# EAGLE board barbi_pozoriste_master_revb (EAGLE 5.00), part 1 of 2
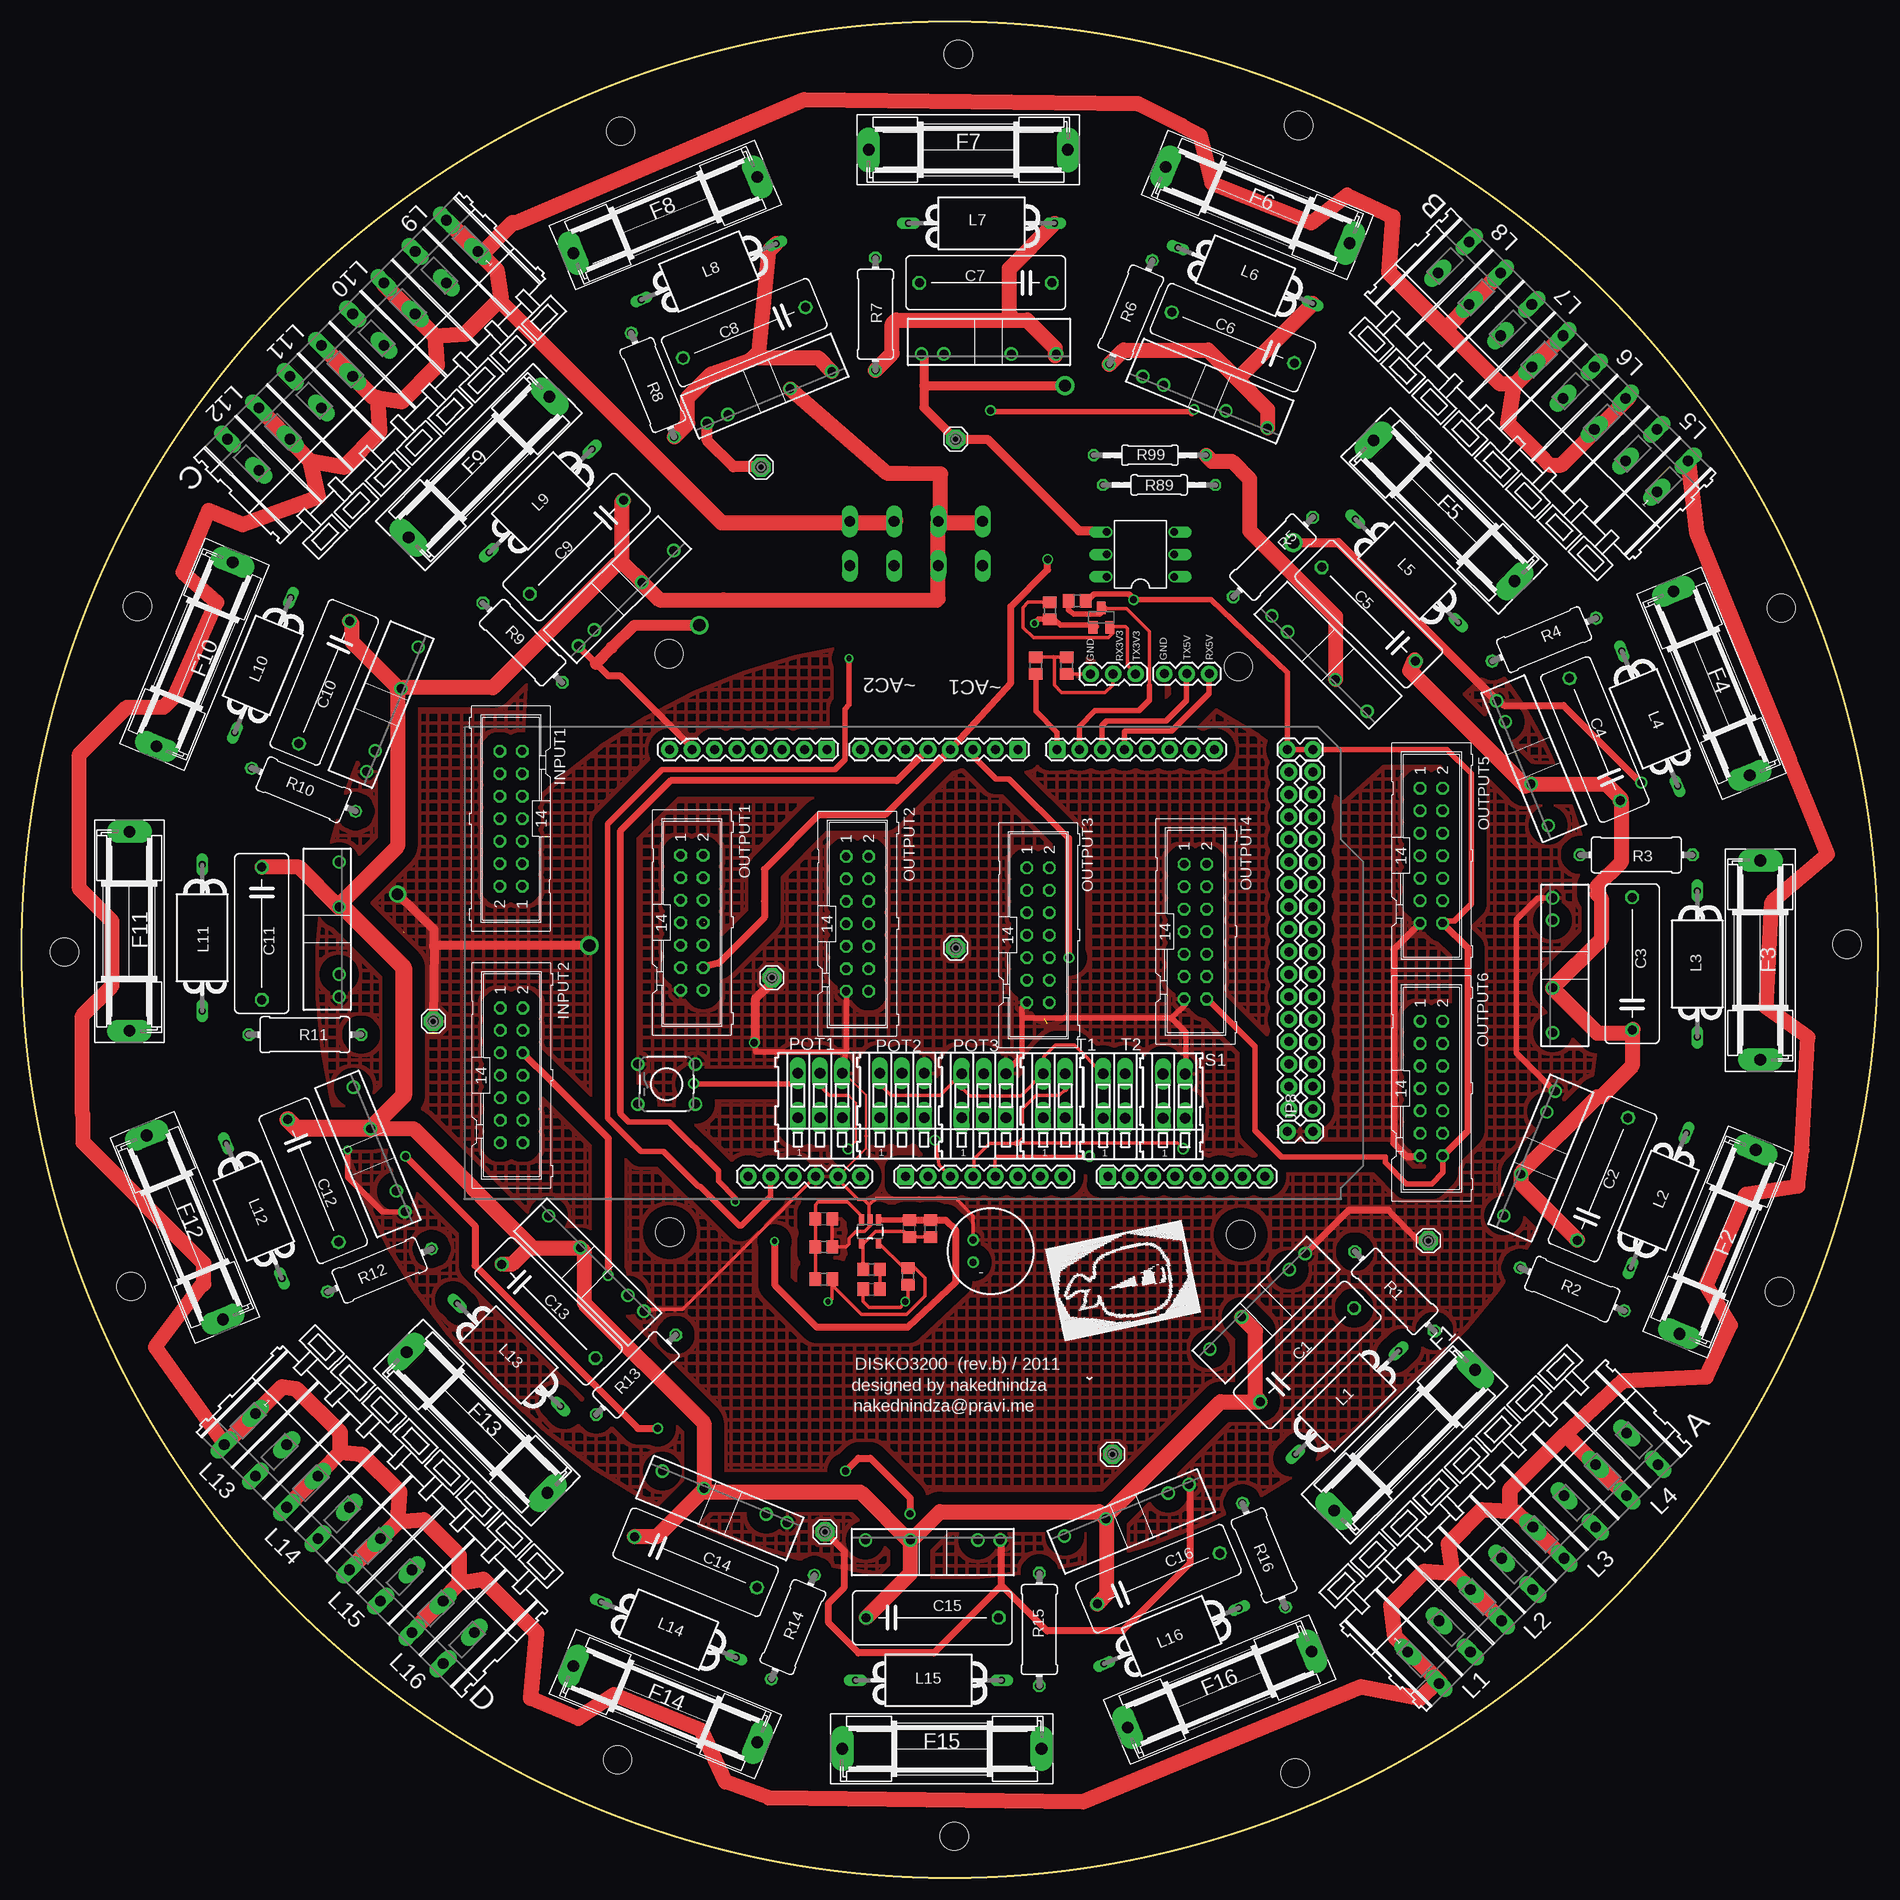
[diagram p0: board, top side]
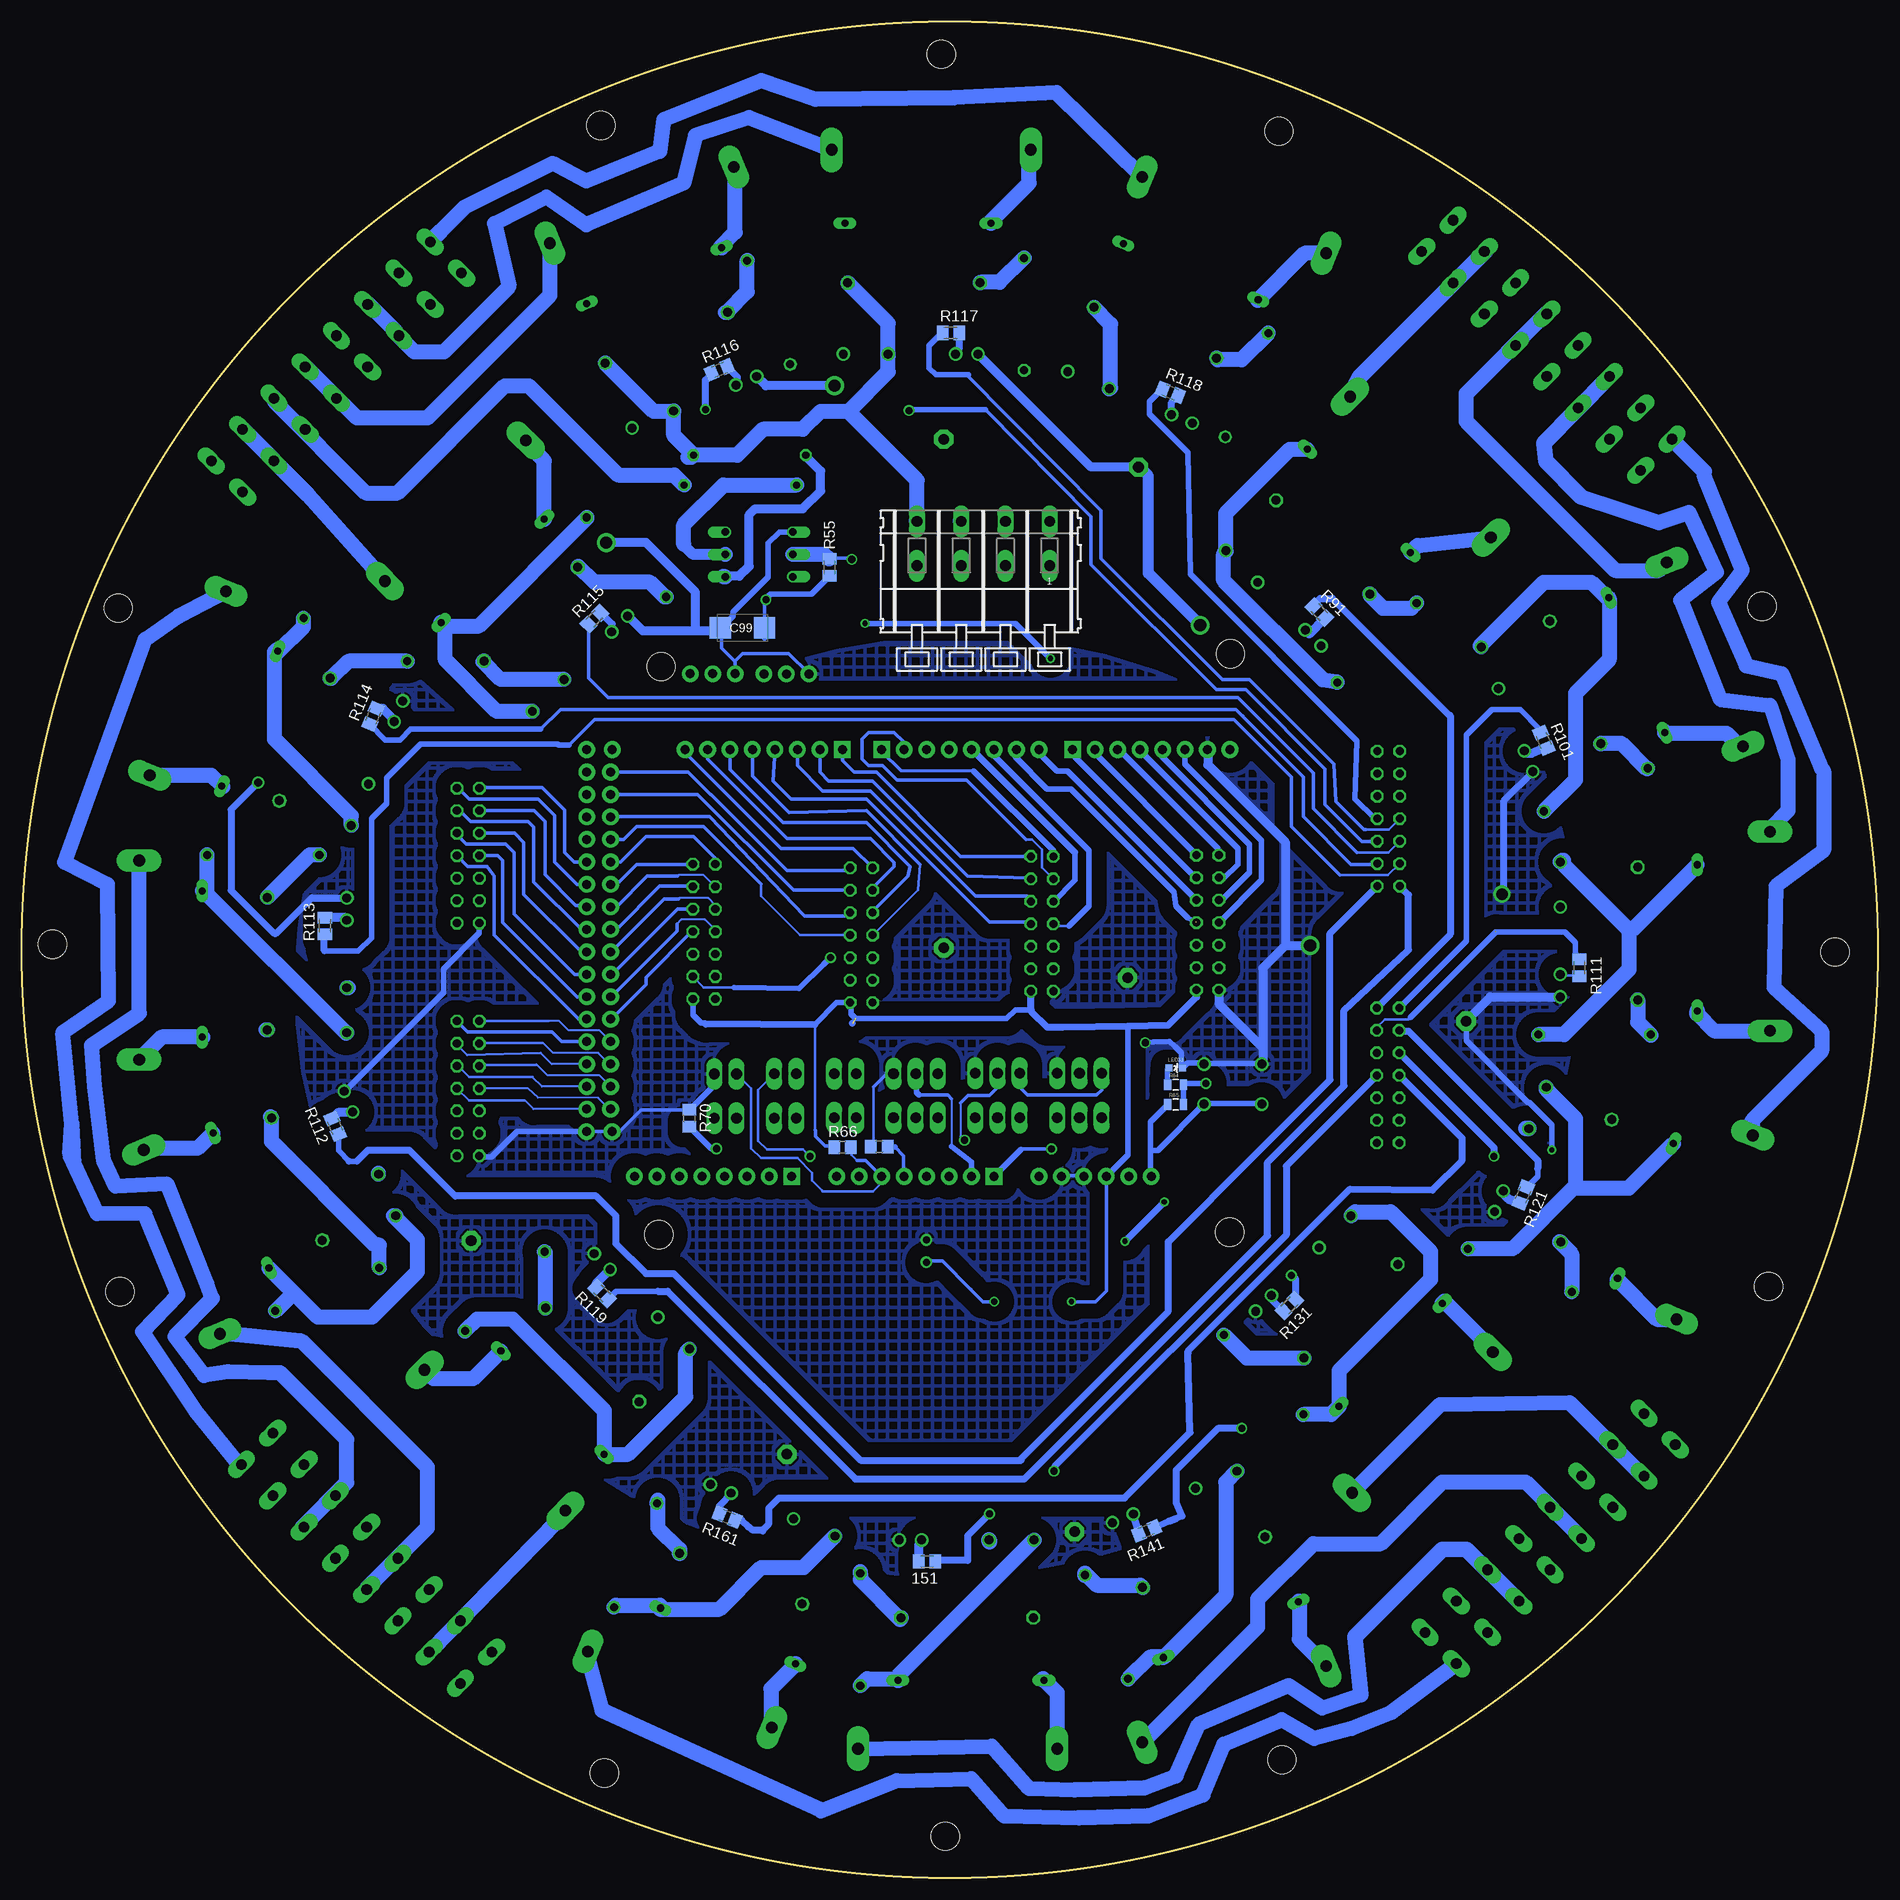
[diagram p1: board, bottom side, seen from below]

No outline drawn. Coordinates in mm, seen from the top.
Copper layers (1*16): Top 0.035mm / dielectric 1.5mm / Bottom 0.035mm
Design rules "default": minimum track width 10mil, minimum drill 24mil, track to track 8mil, track to pad 8mil, pad to pad 8mil, via to via 8mil, smd to smd 8mil, copper to edge 40mil, drill to drill 8mil, minimum pad ring 10mil, minimum via ring 8mil, stop-mask expansion 4mil, vias tented up to drill 0mil, thermal gap 10mil
Holes 3.2 mm at -32.4,33.23 32.21,-32.42 -32.33,-32.15 31.94,31.79 -37.88,92.31 38.37,-93.28 -93.23,-38.28 -38.24,-91.8 38.76,92.95 93.31,38.39 -92.5,38.6 93.12,-38.88 0.27,101 -100.74,-0.47 -0.17,-100.44 100.73,0.41
Milling: area -105.5,-105.1 to 104.2,104.6

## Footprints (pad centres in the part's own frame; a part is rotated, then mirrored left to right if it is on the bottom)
M0805 = smd 1.3 x 1.6: 1 -0.95,0; 2 0.95,0
C150-064X183 = drill 1.016 octagon: 1 -7.493,0; 2 7.493,0
C0805 = smd 1.3 x 1.5: 1 -0.95,0; 2 0.95,0
SMC_C = smd 2.4 x 2.4: + -2.5,0; - 2.5,0
SH22,5 = drill 1.321 pad 2.54 long: 1 -11.252,0; 2 11.252,0
1X03 = drill 1.016 pad 1.88 round: 1 0,0; 2 2.54,0; 3 5.08,0
1X08 = drill 1.016 pad 1.88 square: 1 0,0 | drill 1.016 pad 1.88 round: 2 2.54,0; 3 5.08,0; 4 7.62,0; 5 10.16,0; 6 12.7,0; 7 15.24,0; 8 17.78,0
1X16 = drill 1.016 pad 1.88 round: 1 0,0; 2 2.54,0; 3 5.08,0; 4 7.62,0; 5 10.16,0; 6 12.7,0; 7 15.24,0; 8 17.78,0; 9 20.32,0; 10 22.86,0; 11 25.4,0; 12 27.94,0; 13 30.48,0; 14 33.02,0; 15 35.56,0; 16 38.1,0
1X06 = drill 1.016 pad 1.88 round: 1 0,0; 2 2.54,0; 3 5.08,0; 4 7.62,0; 5 10.16,0; 6 12.7,0
1X02_LOCK = drill 1.016 pad 1.88 round: 1 -0.178,0; 2 2.718,0
S102S01 = drill 1 round: 1 -7.62,0; 2 -2.54,0; 3 5.08,0; 4 7.62,0
ZD6-2W5 = drill 0.8 long: 1 -8.255,0; 2 8.255,0
LED-0603 = smd 0.8 x 0.8: A 0,-0.75; C 0,0.75
MCS08 = drill 1.194 pad 2.159 octagon: MP 0,0
DIL06 = drill 0.813 offset: 1 -2.54,-3.81; 2 0,-3.81; 3 2.54,-3.81; 4 2.54,3.81; 5 0,3.81; 6 -2.54,3.81
SOT23 = smd 1 x 1.4: 1 -0.95,-1.1; 2 0.95,-1.1; 3 0,1.1
0411/12 = drill 0.914 octagon: 1 -6.35,0; 2 6.35,0
R0805 = smd 1.3 x 1.5: 1 -0.95,0; 2 0.95,0
0805 = smd 0.8 x 1.2: 1 -0.9,0; 2 0.9,0
0207/12 = drill 0.813 octagon: 1 -6.35,0; 2 6.35,0
TACTILE-PTH = drill 1.016 round: 1 -3.251,2.261; 2 3.251,2.261; 3 -3.251,-2.261; 4 3.251,-2.261
ML14 = drill 0.914 octagon: 1 -7.62,-1.27; 2 -7.62,1.27; 3 -5.08,-1.27; 4 -5.08,1.27; 5 -2.54,-1.27; 6 -2.54,1.27; 7 0,-1.27; 8 0,1.27; 9 2.54,-1.27; 10 2.54,1.27; 11 5.08,-1.27; 12 5.08,1.27; 13 7.62,-1.27; 14 7.62,1.27
MIC-9.7MM = drill 0.8 round: 1 -2,1.27; 2 -2,-1.27
SOT23-5 = smd 0.55 x 1.2: 1 -0.95,-1.3; 2 0,-1.3; 3 0.95,-1.3; 4 0.95,1.3; 5 -0.95,1.3
255-404-5 = drill 1.2 long: A1 -7.5,0; A2 -2.5,0; A3 2.5,0; A4 7.5,0; B1 -7.5,-5; B2 -2.5,-5; B3 2.5,-5; B4 7.5,-5
255-408-5 = drill 1.2 long: A1 -17.5,0; A2 -12.5,0; A3 -7.5,0; A4 -2.5,0; A5 2.5,0; A6 7.5,0; A7 12.5,0; A8 17.5,0; B1 -17.5,-5; B2 -12.5,-5; B3 -7.5,-5; B4 -2.5,-5; B5 2.5,-5; B6 7.5,-5; B7 12.5,-5; B8 17.5,-5
233-103 = drill 1.2 long: A1 -2.5,2.5; A2 0,2.5; A3 2.5,2.5; B1 -2.5,-2.5; B2 0,-2.5; B3 2.5,-2.5
233-102 = drill 1.2 long: A1 -1.25,2.5; A2 1.25,2.5; B1 -1.25,-2.5; B2 1.25,-2.5

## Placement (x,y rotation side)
151  330R  [M0805]  1.88,-69.37 180 bottom
C1  68nF  [C150-064X183]  39.73,-46.02 45 top
C2  68nF  [C150-064X183]  73.11,-26.14 67.5 top
C3  68nF  [C150-064X183]  76.46,-1.79 90 top
C4  68nF  [C150-064X183]  72.24,23.54 112.5 top
C5  68nF  [C150-064X183]  46.68,37.73 135 top
C6  68nF  [C150-064X183]  31.33,68.96 157.5 top
C7  68nF  [C150-064X183]  3.38,75.17 180 top
C8  68nF  [C150-064X183]  -23.91,69.53 202.5 top
C9  68nF  [C150-064X183]  -42.85,45.3 225 top
C10  68nF  [C150-064X183]  -71.38,30 247.5 top
C11  68nF  [C150-064X183]  -78.45,1.61 270 top
C12  68nF  [C150-064X183]  -72.62,-26.34 292.5 top
C13  68nF  [C150-064X183]  -46.03,-41.08 315 top
C14  68nF  [C150-064X183]  -29.4,-69.45 337.5 top
C15  68nF  [C150-064X183]  -2.64,-75.73 0 top
C16  68nF  [C150-064X183]  22.92,-71.3 22.5 top
C17  4.7uF  [C0805]  -9.52,-38.58 0 top
C18  12pF  [C0805]  -5.24,-31.75 90 top
C19  1uF  [C0805]  -14.92,-30.64 180 top
C99  47uF  [SMC_C]  22.74,36.17 180 bottom
F1  3A  [SH22,5]  50.73,-55.68 225 top
F2  3A  [SH22,5]  86.12,-33.24 247.5 top
F3  3A  [SH22,5]  90.94,-1.38 90 top
F4  3A  [SH22,5]  85.45,29.88 112.5 top
F5  3A  [SH22,5]  55.21,49.4 315 top
F6  3A  [SH22,5]  34.11,83.96 337.5 top
F7  3A  [SH22,5]  1.42,90.2 0 top
F8  3A  [SH22,5]  -32.84,82.81 22.5 top
F9  3A  [SH22,5]  -53.89,54.33 45 top
F10  3A  [SH22,5]  -86.03,33.17 67.5 top
F11  3A  [SH22,5]  -93.42,1.87 90 top
F12  3A  [SH22,5]  -87.15,-31.6 112.5 top
F13  3A  [SH22,5]  -54.11,-53.65 315 top
F14  3A  [SH22,5]  -32.83,-85.5 337.5 top
F15  3A  [SH22,5]  -1.57,-90.53 0 top
F16  3A  [SH22,5]  29.84,-83.84 22.5 top
JP1  [1X03]  23.57,30.97 0 top
JP2  [1X03]  15.24,30.96 0 top
JP3  [1X08]  -14.57,22.41 180 top
JP4  [1X08]  7.02,22.41 180 top
JP5  [1X08]  11.46,22.41 0 top
JP6  [1X08]  17.18,-25.85 0 top
JP7  [1X08]  -5.68,-25.85 0 top
JP8  M16PTH  [1X16]  40.36,-18.23 90 top
JP9  M16PTH  [1X16]  37.66,-18.23 90 top
JP10  [1X06]  -23.46,-25.85 0 top
JP11  [1X02_LOCK]  37.67,-20.77 0 top
JP12  [1X02_LOCK]  37.65,22.41 0 top
K1  S202S01  [S102S01]  34.12,-39.96 45 top
K2  S202S01  [S102S01]  64.87,-23.25 67.5 top
K3  S202S01  [S102S01]  67.48,-1.98 90 top
K4  S202S01  [S102S01]  64.06,20.87 112.5 top
K5  S202S01  [S102S01]  41.12,32.11 135 top
K6  S202S01  [S102S01]  28.19,61.66 157.5 top
K7  S202S01  [S102S01]  3.74,67.11 180 top
K8  S202S01  [S102S01]  -21.06,62.22 202.5 top
K9  S202S01  [S102S01]  -37.27,39.52 225 top
K10  S202S01  [S102S01]  -63.68,26.96 247.5 top
K11  S202S01  [S102S01]  -69.69,2.08 270 top
K12  S202S01  [S102S01]  -65.18,-22.79 292.5 top
K13  S202S01  [S102S01]  -40.64,-35.69 315 top
K14  S202S01  [S102S01]  -26.12,-62.07 337.5 top
K15  S202S01  [S102S01]  -2.58,-66.94 0 top
K16  S202S01  [S102S01]  19.33,-63.58 22.5 top
L1  300uH  [ZD6-2W5]  44.22,-51.41 45 top
L2  300uH  [ZD6-2W5]  79.44,-28.56 67.5 top
L3  300uH  [ZD6-2W5]  83.81,-1.83 270 top
L4  300uH  [ZD6-2W5]  78.45,25.89 292.5 top
L5  300uH  [ZD6-2W5]  50.99,42.6 135 top
L6  300uH  [ZD6-2W5]  32.73,75.97 157.5 top
L7  300uH  [ZD6-2W5]  2.91,81.89 180 top
L8  300uH  [ZD6-2W5]  -27.92,76.44 202.5 top
L9  300uH  [ZD6-2W5]  -46.93,50.52 225 top
L10  300uH  [ZD6-2W5]  -78.33,31.94 247.5 top
L11  300uH  [ZD6-2W5]  -85.17,1.12 270 top
L12  300uH  [ZD6-2W5]  -79.33,-29.75 292.5 top
L13  300uH  [ZD6-2W5]  -50.52,-46.02 135 top
L14  300uH  [ZD6-2W5]  -32.45,-77.07 157.5 top
L15  300uH  [ZD6-2W5]  -3.07,-82.8 180 top
L16  300uH  [ZD6-2W5]  24.39,-77.79 202.5 top
LED33  Red  [LED-0603]  -26.21,-13.58 270 bottom
LSP1  MCS08  [MCS08]  -20.79,-3.38 315 top
LSP2  MCS08  [MCS08]  -14.8,-66 315 top
LSP3  MCS08  [MCS08]  53.43,-33.11 315 top
LSP4  MCS08  [MCS08]  0,-0.01 315 top
LSP5  MCS08  [MCS08]  -0.01,57.48 315 top
LSP6  MCS08  [MCS08]  -22.01,54.33 315 top
LSP7  MCS08  [MCS08]  -59.05,-8.3 315 top
LSP8  MCS08  [MCS08]  17.73,-57.25 315 top
OK1  H11A1M  [DIL06]  20.87,44.47 90 top
Q1  BSS123  [SOT23]  16.45,37.34 0 top
R1  120R 2W  [0411/12]  49.61,-38.84 135 top
R2  120R 2W  [0411/12]  69.68,-38.6 337.5 top
R3  120R 2W  [0411/12]  76.92,10.5 0 top
R4  120R 2W  [0411/12]  66.5,34.84 22.5 top
R5  120R 2W  [0411/12]  35.86,44.16 45 top
R6  120R 2W  [0411/12]  19.79,71.82 247.5 top
R7  120R 2W  [0411/12]  -9.08,71.62 270 top
R8  120R 2W  [0411/12]  -34.25,63.61 292.5 top
R9  120R 2W  [0411/12]  -48.96,34.49 135 top
R10  120R 2W  [0411/12]  -73.71,17.86 337.5 top
R11  120R 2W  [0411/12]  -73.57,-9.82 0 top
R12  120R 2W  [0411/12]  -65.13,-36.46 22.5 top
R13  120R 2W  [0411/12]  -36.15,-48.27 225 top
R14  120R 2W  [0411/12]  -18.41,-76.78 247.5 top
R15  120R 2W  [0411/12]  9.44,-77.06 270 top
R16  120R 2W  [0411/12]  34.84,-68.66 292.5 top
R17  2k2  [R0805]  -5.4,-37.15 90 top
R18  10k  [R0805]  9.05,31.91 90 top
R19  10k  [R0805]  12.54,31.91 270 top
R20  10k  [R0805]  -9.53,-36.35 0 top
R21  10k  [R0805]  -14.92,-37.46 0 top
R22  10k  [R0805]  -14.92,-33.81 180 top
R23  1M  [R0805]  -2.86,-31.75 270 top
R24  10k  [R0805]  10.64,38.1 90 top
R25  10k  [R0805]  13.72,39.21 180 top
R55  10k  [M0805]  12.92,43.01 270 bottom
R64  330  [0805]  -26.21,-15.49 0 bottom
R65  10k  [0805]  -26.21,-17.71 0 bottom
R66  1k  [R0805]  11.44,-22.53 0 bottom
R70  10k  [R0805]  28.76,-19.28 270 bottom
R71  10k  [R0805]  7.28,-22.49 0 bottom
R89  47k 1W  [0207/12]  22.99,52.31 0 top
R91  330R  [M0805]  -42.44,37.94 315 bottom
R99  47k 1W  [0207/12]  21.94,55.68 0 top
R101  330R  [M0805]  -67.82,23.44 292.5 bottom
R111  330R  [M0805]  -71.85,-2.24 270 bottom
R112  330R  [M0805]  68.78,-20.18 112.5 bottom
R113  330R  [M0805]  69.95,2.47 90 bottom
R114  330R  [M0805]  64.5,26.17 67.5 bottom
R115  330R  [M0805]  39.49,37.19 45 bottom
R116  330R  [M0805]  25.36,65.33 22.5 bottom
R117  330R  [M0805]  -0.81,69.51 0 bottom
R118  330R  [M0805]  -25.61,62.78 337.5 bottom
R119  330R  [M0805]  38.61,-39.06 135 bottom
R121  330R  [M0805]  -65.49,-27.94 247.5 bottom
R131  330R  [M0805]  -39.07,-40.41 225 bottom
R141  330R  [M0805]  -22.92,-65.92 202.5 bottom
R161  330R  [M0805]  24.48,-64.35 157.5 bottom
S1  [TACTILE-PTH]  -32.69,-15.41 0 top
SV1  [ML14]  -50.28,14.6 90 top
SV2  [ML14]  -29.83,2.84 270 top
SV3  [ML14]  -11.11,2.7 270 top
SV4  [ML14]  9.32,1.43 270 top
SV5  [ML14]  27.09,1.83 270 top
SV6  [ML14]  53.77,-15.9 270 top
SV7  [ML14]  53.76,10.41 270 top
SV8  [ML14]  -50.22,-14.42 270 top
U$1  MIC9.7MM  [MIC-9.7MM]  3.97,-34.29 0 top
U$2  OPA344  [SOT23-5]  -9.68,-32.07 180 top
X1  WAGO4-255-404-5  [255-404-5]  -4.48,43.19 180 bottom
X2  WAGO8-255-408-5  [255-408-5]  -66.4,66.33 225 top
X3  WAGO8-255-408-5  [255-408-5]  -66.78,-65.01 315 top
X5  WAGO8-255-408-5  [255-408-5]  63.47,-67.24 45 top
X6  WAGO8-255-408-5  [255-408-5]  66.88,63.89 135 top
X10  [233-103]  -15.35,-16.69 0 top
X11  [233-103]  3.17,-16.72 0 top
X12  [233-103]  -6.08,-16.7 0 top
X13  [233-102]  11.14,-16.72 0 top
X14  [233-102]  17.91,-16.75 0 top
X15  [233-102]  24.67,-16.76 0 top

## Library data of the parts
151 C1-C19 C99 R1-R25 R55 R66 R70 R71 R89 R91 R99 R101 R111-R119 R121 R131 R141 R161 = rcl
F1-F16 = fuse
JP1-JP12 LED33 R64 R65 S1 U$1 U$2 = SparkFun
K1-K16 = relay
L1-L16 = inductor-neosid
LSP1-LSP8 = solpad
OK1 = optocoupler
Q1 = transistor-small-signal
SV1-SV8 = con-ml
X1-X3 X5 X6 X10-X15 = con-wago

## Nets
3.3: JP10.2 Q1.1 R24.1
5V: R64.2 R65.2 X10.A1 X11.A1 X12.A1 X13.A1 X14.A1
A0: JP7.1 X10.A2
A1: JP7.2 X11.A2
A2: JP7.3 X12.A2
A3: JP7.4 R70.2 X13.A2
A4: JP7.5 R71.2 X14.A2
A5: JP7.6 R66.2 X15.A1
A6: JP7.7
A7: JP7.8
A8: JP6.1
A9: JP6.2
A10: JP6.3
A11: JP6.4
A12: JP6.5
A13: JP6.6
A14: JP6.7
A15: JP6.8
AC_NEUTRAL: R89.2 X1.B1 X1.B2 X2.B1 X2.B3 X2.B5 X2.B7 X3.B1 X3.B3 X3.B5 X3.B7 X5.B1 X5.B3 X5.B5 X5.B7 X6.B1 X6.B3 X6.B5 X6.B7
AC_PHASE: C1.1 C2.1 C3.1 C4.1 C5.1 C6.1 C7.1 C8.1 C9.1 C10.1 C11.1 C12.1 C13.1 C14.1 C15.1 C16.1 K1.2 K2.2 K3.2 K4.2 K5.2 K6.2 K7.2 K8.2 K9.2 K10.2 K11.2 K12.2 K13.2 K14.2 K15.2 K16.2 R99.2 X1.B3 X1.B4
AREF: JP3.8
D2: JP4.3 SV5.12
D3: JP4.4 OK1.5 R55.1 SV2.12
D4: C18.2 JP4.5 R23.1 SV3.5 U$2.1
D5: JP4.6 SV3.7
D6: JP4.7 SV2.8
D7: JP4.8 SV2.6
D8: JP3.1 SV2.4
D9: JP3.2 SV2.2
D10: JP3.3 SV2.1
D11: JP3.4 SV2.3
D12: JP3.5 SV2.5
D13: JP3.6 SV2.7
D14: JP5.1 R18.1 SV3.2
D15: JP5.2 Q1.3 R25.2 SV3.4
D16: JP1.2 JP5.3 SV3.6
D17: JP1.3 JP5.4 SV3.8
D18: JP5.5 SV4.7
D19: JP5.6 SV4.5
D22: JP9.16 SV4.2
D23: JP8.16
D24: JP9.15 SV4.4
D25: JP8.15
D26: JP9.14 SV4.6
D27: JP8.14
D28: JP9.13 SV4.8
D29: JP8.13
D30: JP9.12 SV5.1
D31: JP8.12 SV7.1
D32: JP9.11 SV5.2
D33: JP8.11 SV7.2
D34: JP9.10 SV5.3
D35: JP8.10 SV7.3
D36: JP9.9 SV5.4
D37: JP8.9 SV7.4
D38: JP9.8 SV5.5
D39: JP8.8 SV7.5
D40: JP9.7 SV5.6
D41: JP8.7 SV7.6
D42: JP9.6 SV5.7
D43: JP8.6 SV7.7
D44: JP9.5 SV5.8
D45: JP8.5 SV7.8
D46: JP9.4 SV6.1
D47: JP8.4 SV6.2
D48: JP9.3 SV6.3
D49: JP8.3 SV6.4
D50: JP9.2 SV6.5
D51: JP8.2 SV6.6
D52: JP9.1 SV6.7
D53: JP8.1 SV6.8
GND: C19.1 C99.- JP1.1 JP2.1 JP3.7 JP10.4 JP10.5 JP11.1 JP11.2 K1.4 K2.4 K3.4 K4.4 K5.4 K6.4 K7.4 K8.4 K9.4 K10.4 K11.4 K12.4 K13.4 K14.4 K15.4 K16.4 LED33.C LSP1.MP LSP2.MP LSP3.MP LSP4.MP LSP5.MP LSP6.MP LSP7.MP LSP8.MP OK1.4 R19.2 R22.1 R70.1 R71.1 S1.1 S1.2 SV2.13 SV3.13 SV4.13 SV5.13 SV6.13 SV7.13 U$1.1 U$2.2 X10.A3 X11.A3 X12.A3 X15.A2
INPUT1: R119.1 SV1.2
INPUT2: R112.1 SV1.1
INPUT3: R113.1 SV1.4
INPUT4: R114.1 SV1.3
INPUT5: R115.1 SV1.6
INPUT6: R116.1 SV1.5
INPUT7: R117.1 SV1.8
INPUT8: R118.1 SV1.7
INPUT9: R91.1 SV8.2
INPUT10: R101.1 SV8.1
INPUT11: R111.1 SV8.4
INPUT12: R121.1 SV8.3
INPUT13: R131.1 SV8.6
INPUT14: R141.1 SV8.5
INPUT15: 151.1 SV8.8
INPUT16: R161.1 SV8.7
LAMP1: F1.1 L1.2
LAMP2: F2.1 L2.2
LAMP3: F3.1 L3.2
LAMP4: F4.1 L4.2
LAMP5: F5.1 L5.2
LAMP6: F6.1 L6.2
LAMP7: F7.1 L7.2
LAMP8: F8.1 L8.2
LAMP9: F9.1 L9.2
LAMP10: F10.1 L10.2
LAMP11: F11.1 L11.2
LAMP12: F12.1 L12.2
LAMP13: F13.1 L13.2
LAMP14: F14.1 L14.2
LAMP15: F15.1 L15.2
LAMP16: F16.1 L16.2
N$1: K2.1 L2.1 R2.2
N$2: K1.1 L1.1 R1.1
N$3: C1.2 R1.2
N$4: C2.2 R2.1
N$5: F4.2 X5.B8
N$6: K3.1 L3.1 R3.2
N$7: OK1.1 R99.1
N$8: C3.2 R3.1
N$9: F1.2 X5.B2
N$10: F2.2 X5.B4
N$11: C4.2 R4.1
N$12: K4.1 L4.1 R4.2
N$13: K5.1 L5.1 R5.2
N$14: OK1.2 R89.1
N$15: C5.2 R5.1
N$16: F3.2 X5.B6
N$17: K6.1 L6.1 R6.2
N$18: C6.2 R6.1
N$19: F5.2 X6.B2
N$20: F8.2 X6.B8
N$21: C7.2 R7.1
N$22: K7.1 L7.1 R7.2
N$23: K8.1 L8.1 R8.2
N$24: C8.2 R8.1
N$25: F7.2 X6.B6
N$26: F6.2 X6.B4
N$27: K2.3 R112.2
N$28: K3.3 R113.2
N$29: K4.3 R114.2
N$30: K5.3 R115.2
N$31: K6.3 R116.2
N$32: K7.3 R117.2
N$33: K8.3 R118.2
N$34: K1.3 R119.2
N$36: K10.3 R101.2
N$38: K11.3 R111.2
N$40: K12.3 R121.2
N$42: K13.3 R131.2
N$44: K14.3 R141.2
N$46: 151.2 K15.3
N$48: K16.3 R161.2
N$50: K9.3 R91.2
N$59: K9.1 L9.1 R9.1
N$60: C9.2 R9.2
N$61: K10.1 L10.1 R10.2
N$62: C10.2 R10.1
N$63: K11.1 L11.1 R11.2
N$64: C11.2 R11.1
N$65: C12.2 R12.1
N$66: K12.1 L12.1 R12.2
N$67: K13.1 L13.1 R13.2
N$68: C13.2 R13.1
N$69: K14.1 L14.1 R14.2
N$70: C14.2 R14.1
N$71: C15.2 R15.1
N$72: K15.1 L15.1 R15.2
N$73: K16.1 L16.1 R16.2
N$74: C16.2 R16.1
N$75: C17.1 R17.1 U$1.2
N$79: C19.2 R21.1 R22.2 U$2.3
N$80: C17.2 R20.2
N$81: C18.1 R20.1 R23.2 U$2.4
N$139: F12.2 X2.B8
N$140: F9.2 X2.B2
N$141: F10.2 X2.B4
N$142: F11.2 X2.B6
N$143: F13.2 X3.B2
N$144: F16.2 X3.B8
N$145: F15.2 X3.B6
N$146: F14.2 X3.B4
N$163: LED33.A R64.1
RES: JP10.1 R65.1 S1.3 S1.4
RX0: JP4.1 SV3.1
RX3V3: JP2.2 R18.2 R19.1
SCL: JP5.8 SV4.1
SDA: JP5.7 SV4.3
TX1: JP4.2 SV3.3
TX3V3: JP2.3 Q1.2 R24.2
VCC: C99.+ JP10.3 JP12.1 JP12.2 R17.2 R21.2 R25.1 R55.2 R66.1 SV2.14 SV3.14 SV4.14 SV5.14 SV6.14 SV7.14 U$2.5
VIN: JP10.6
